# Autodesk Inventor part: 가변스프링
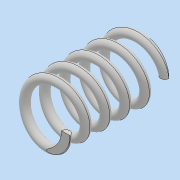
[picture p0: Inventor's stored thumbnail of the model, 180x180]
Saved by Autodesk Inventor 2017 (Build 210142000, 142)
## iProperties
Part Number: 가변스프링
Material: 일반
Document SubType Name: Modeling
Designer: 00-00
Density: 1 g/cm^3
Appearance: 기본값
Author: 00-00
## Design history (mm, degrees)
sketch "스케치1"
  geometry: L1 (0, 0)-(6, 0); L2 (6, 0)-(6, 23.5); L3 (6, 23.5)-(0, 23.5); L4 (0, 23.5)-(0, 0); C1 r 1 at (6, 0)
  constraints: 8 end point, 2 parallel, 1 centre point, 1 coincident, 1 horizontal, 1 perpendicular
  dimensions: "d0" = 23.5 distance of L3.end L1.start (derived); "d1" = 6 distance of L2.end L3.end; "d2" = 2 diameter of C1
feature "코일1" sketch "스케치1" pitch "d3" = 23.5 (= d0); turns "d5" = 5; dims "d4" = 23.5 (= d0), "d6" = 0, angle "d7" = 90 deg, angle "d8" = 90 deg, "d9" = 0, "d10" = 0
sketch "스케치2"
  geometry: L1 (0, 15.313)-(23.5, 15.313); L2 (23.5, 15.313)-(23.5, -15.313); L3 (23.5, -15.313)-(0, -15.313); L4 (0, -15.313)-(0, 15.313); 2 further points
  constraints: 8 end point, 2 parallel, 1 coincident, 1 horizontal, 1 midpoint, 1 perpendicular
  dimensions: "d11" = 23.5 distance of L2.end L3.end (= d0); "d14" = 30.62624 distance of L1.end L2.end
extrude "돌출2" sketch "스케치2" stored distance "d15" = 20; taper "d16" = 0 deg
node "솔리드1"
